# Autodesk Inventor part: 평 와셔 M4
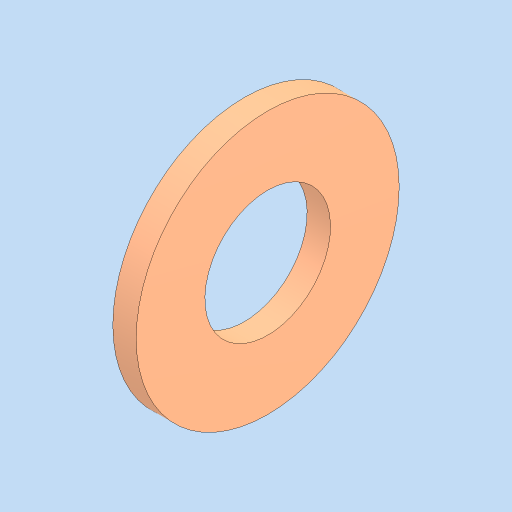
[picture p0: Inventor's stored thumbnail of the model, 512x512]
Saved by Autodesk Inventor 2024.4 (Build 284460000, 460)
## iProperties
Created: 2026-07
Part Number: 평 와셔 M4
Material: 강철, 연강
Description: 평면 와셔
Document SubType Name: Modeling
Designer: home
Density: 7.85 g/cm^3
Appearance: 기본값
Author: jhkim
Sending System: Autodesk Inventor 2027
Preprocessor: ST-DEVELOPER v20.1
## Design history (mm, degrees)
feature "Solid1"
node "솔리드1"
